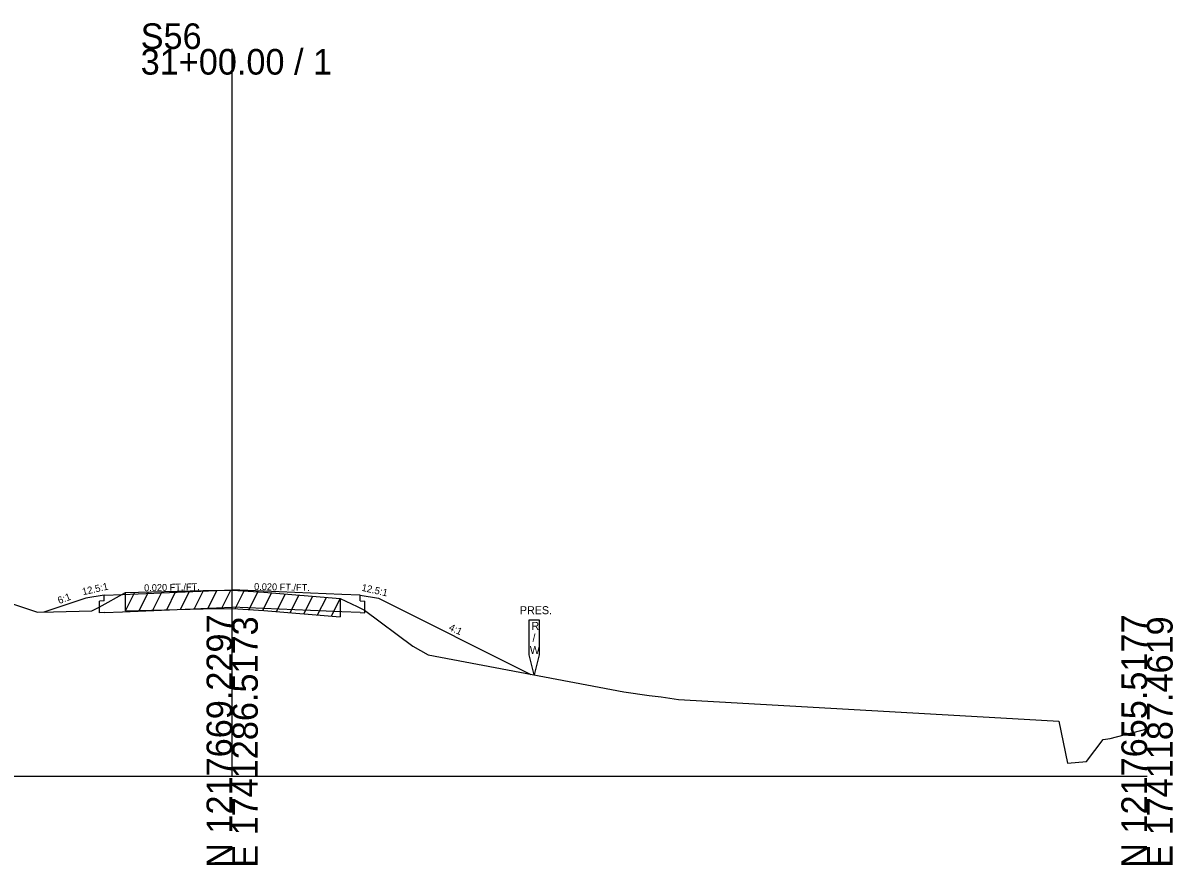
# Model space of a CAD drawing. Extents: x -26 to 1203, y -10 to 19541.
# Drawn here: x 77.1 to 202.8, y 5990.3 to 6082.3 of the extents above; entities that cross this region are included whole.
import ezdxf

# ---------------------------------------------------------------- set-up
doc = ezdxf.new("R2010")
doc.units = 0
for name, color, linetype in [('RD_GPK_XS_Cell', 7, 'Continuous'), ('RD_XS_Base', 7, 'Continuous'), ('RD_XS_EarthShd', 7, 'Continuous'), ('RD_XS_ExGround', 7, 'Continuous'), ('RD_XS_ExPaveRet', 7, 'Continuous'), ('RD_XS_ExRW', 7, 'Continuous'), ('RD_XS_Pave', 7, 'Continuous'), ('RD_XS_TX_Elev_EX', 7, 'Continuous'), ('RD_XS_TX_Slope', 7, 'Continuous')]:
    doc.layers.add(name, color=color, linetype=linetype)

msp = doc.modelspace()

# ---------------------------------------------------------------- linework, layer by layer
at = {"layer": 'RD_GPK_XS_Cell'}
for p, q in [((100, 6000), (100, 6079.49)), ((0, 6000), (100, 6000)), ((100, 6000), (200, 6000))]:
    msp.add_line(p, q, dxfattribs=at)
at = {"layer": 'RD_XS_Base'}
for p, q in [((86, 6019.16), (85.5, 6019.14)), ((85.5, 6017.87), (85.5, 6019.14)), ((86, 6019.16), (86, 6019.8)), ((114, 6019.16), (114, 6019.8)), ((114, 6019.16), (114.5, 6019.14)), ((114.5, 6017.87), (114.5, 6019.14)), ((86, 6017.89), (85.5, 6017.87)), ((86, 6017.89), (88, 6017.98)), ((88, 6017.98), (100, 6018.48)), ((112, 6017.98), (100, 6018.48)), ((114, 6017.89), (112, 6017.98)), ((114, 6017.89), (114.5, 6017.87))]:
    msp.add_line(p, q, dxfattribs=at)
at = {"layer": 'RD_XS_EarthShd'}
for p, q in [((84, 6019.47), (79.42, 6017.94)), ((86, 6019.8), (84, 6019.47)), ((114, 6019.8), (116, 6019.47)), ((116, 6019.47), (132.65, 6011.14))]:
    msp.add_line(p, q, dxfattribs=at)
at = {"layer": 'RD_XS_ExGround'}
msp.add_lwpolyline([(72.22, 6020.08), (78.72, 6017.95), (80.48, 6017.97), (84.67, 6018.08), (85.46, 6018.48), (88.34, 6020.08), (96.82, 6020.29), (100.02, 6020.34), (103.47, 6020.11), (111.81, 6019.42), (113.67, 6018.57), (114.45, 6018.15), (119.76, 6014.24), (121.41, 6013.26), (142.81, 6009.23), (145.57, 6008.84), (146.91, 6008.67), (148.79, 6008.41), (186.56, 6006.23), (190.35, 6006.01), (191.31, 6001.43), (193.37, 6001.61), (195.22, 6004.02), (195.97, 6004.13), (200, 6005.18)], dxfattribs=at)
at = {"layer": 'RD_XS_ExPaveRet'}
for p, q in [((88.34, 6018.08), (89.35, 6020.11)), ((88.34, 6018.08), (88.34, 6020.08)), ((89.84, 6018.12), (90.85, 6020.14)), ((91.34, 6018.16), (92.35, 6020.18)), ((92.84, 6018.19), (93.85, 6020.22)), ((94.34, 6018.23), (95.35, 6020.25)), ((95.84, 6018.26), (96.85, 6020.29)), ((97.34, 6018.3), (98.34, 6020.31)), ((98.84, 6018.32), (99.84, 6020.34)), ((100.34, 6018.32), (101.3, 6020.26)), ((101.84, 6018.22), (102.8, 6020.15)), ((103.34, 6018.12), (104.3, 6020.04)), ((104.84, 6017.99), (105.8, 6019.92)), ((106.34, 6017.87), (107.3, 6019.79)), ((107.84, 6017.75), (108.8, 6019.67)), ((109.34, 6017.63), (110.3, 6019.55)), ((110.84, 6017.5), (111.8, 6019.42)), ((111.81, 6019.42), (111.81, 6017.42)), ((88.34, 6018.08), (96.82, 6018.29)), ((96.82, 6018.29), (100.02, 6018.34)), ((100.02, 6018.34), (103.47, 6018.11)), ((103.47, 6018.11), (111.81, 6017.42))]:
    msp.add_line(p, q, dxfattribs=at)
at = {"layer": 'RD_XS_ExRW'}
msp.add_lwpolyline([(132.45, 6017.09), (133.55, 6017.09), (133.55, 6013.26), (133, 6011.08), (132.45, 6013.26)], close=True, dxfattribs=at)
at = {"layer": 'RD_XS_Pave'}
for p, q in [((88, 6019.88), (100, 6020.38)), ((112, 6019.88), (100, 6020.38)), ((86, 6019.8), (88, 6019.88)), ((114, 6019.8), (112, 6019.88))]:
    msp.add_line(p, q, dxfattribs=at)

# ---------------------------------------------------------------- texts
at = {"layer": 'RD_GPK_XS_Cell'}
for s, p in [('S56', (90, 6079.49)), ('31+00.00 / 1', (90, 6076.69))]:
    msp.add_text(s, height=2.8, dxfattribs=at).set_placement(p)
for s, p in [('N 1217669.2297', (100, 5990)), ('N 1217655.5177', (200, 5990)), ('E 1741286.5173', (102.8, 5990)), ('E 1741187.4619', (202.8, 5990))]:
    msp.add_text(s, height=2.8, rotation=90, dxfattribs=at).set_placement(p)
at = {"layer": 'RD_XS_ExRW'}
for s, p in [('PRES.', (131.45, 6017.72)), ('R', (132.71, 6016)), ('/', (132.83, 6014.69)), ('W', (132.53, 6013.37))]:
    msp.add_text(s, height=0.875, dxfattribs=at).set_placement(p)
at = {"layer": 'RD_XS_TX_Elev_EX'}
msp.add_text('851.17', height=0.1, rotation=90, dxfattribs=at).set_placement((100.1, 6020.34))
at = {"layer": 'RD_XS_TX_Slope'}
for s, height, rotation, p in [('12.5:1', 0.778, 12.7511, (83.69, 6019.78)), ('0.020 FT./FT.', 0.7518, 1.1916, (90.38, 6020.22)), ('0.020 FT./FT.', 0.7518, 358.8084, (102.39, 6020.37)), ('12.5:1', 0.778, 347.2489, (114.09, 6020.29)), ('6:1', 0.778, 20.9309, (81.1, 6018.81)), ('4:1', 0.778, 335.081, (123.61, 6016.01))]:
    msp.add_text(s, height=height, rotation=rotation, dxfattribs=at).set_placement(p)

doc.saveas('drawing.dxf')
